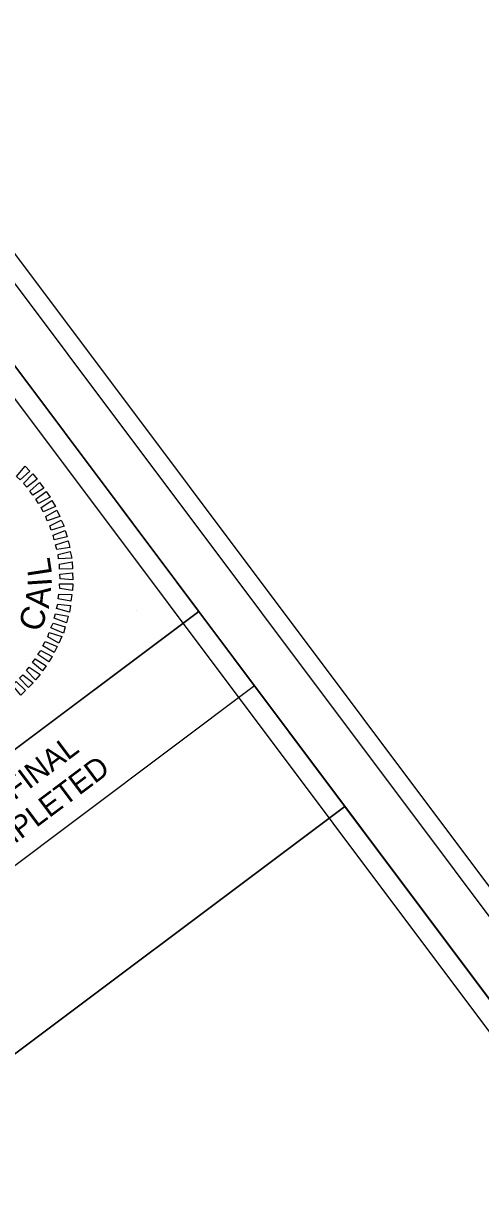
# Model space of a CAD drawing. Extents: x 2186558 to 2188589, y 629855 to 631741.
# Drawn here: x 2187977.7 to 2188093, y 631449 to 631741 of the extents above; entities that cross this region are included whole.
import ezdxf

# ---------------------------------------------------------------- set-up
doc = ezdxf.new("R2010")
doc.units = 0
for name, color, linetype in [('Default', 7, 'Continuous'), ('Scratch_Level_8', 7, 'Continuous'), ('Sheet Plan CELL', 7, 'Continuous'), ('Sheet Plan Layout CELL', 7, 'Continuous'), ('Sheet Plot Border Inside CELL', 7, 'Continuous'), ('Sheet Plot Border Outside CELL', 7, 'Continuous'), ('Sheet Sticker Exception Certification CELL', 7, 'Continuous')]:
    doc.layers.add(name, color=color, linetype=linetype)

msp = doc.modelspace()

# ---------------------------------------------------------------- linework, layer by layer
at = {"layer": 'Default'}
msp.add_line((2188006.11, 631592.93), (2188006.11, 631592.93), dxfattribs=at)
for points in [[(2187976, 631626.73), (2187978.18, 631629.31), (2187979.37, 631628.05), (2187976.93, 631625.91)], [(2187977.74, 631625), (2187980.07, 631627.38), (2187981.19, 631626.06), (2187978.55, 631624.09)], [(2187979.34, 631623.03), (2187981.82, 631625.21), (2187982.86, 631623.83), (2187980.07, 631622.06)], [(2187980.86, 631621.01), (2187983.5, 631622.98), (2187984.45, 631621.55), (2187981.51, 631619.98)], [(2187982.16, 631618.94), (2187984.9, 631620.68), (2187985.77, 631619.19), (2187982.69, 631617.82)], [(2187983.39, 631616.63), (2187986.15, 631618.27), (2187986.9, 631616.68), (2187983.74, 631615.57)], [(2187984.36, 631614.33), (2187987.27, 631615.75), (2187987.99, 631614.21), (2187984.71, 631613.26)], [(2187985.25, 631611.96), (2187988.28, 631613.15), (2187988.73, 631611.53), (2187985.48, 631610.8)], [(2187985.85, 631609.56), (2187989.03, 631610.55), (2187989.4, 631608.87), (2187986.11, 631608.36)], [(2187986.48, 631607.12), (2187989.51, 631607.88), (2187989.89, 631606.2), (2187986.57, 631605.98)], [(2187986.81, 631604.65), (2187990, 631605.2), (2187990.11, 631603.45), (2187986.78, 631603.42)], [(2187986.88, 631602.11), (2187990.11, 631602.44), (2187990.22, 631600.69), (2187986.97, 631600.97)], [(2187986.86, 631599.69), (2187990.19, 631599.72), (2187990.09, 631598), (2187986.87, 631598.49)], [(2187986.67, 631597.07), (2187989.95, 631597), (2187989.71, 631595.3), (2187986.51, 631595.94)], [(2187986.43, 631594.61), (2187989.56, 631594.24), (2187989.31, 631592.54), (2187986.08, 631593.47)], [(2187985.19, 631589.76), (2187988.25, 631588.89), (2187987.81, 631587.29), (2187984.67, 631588.61)], [(2187985.79, 631592.17), (2187989.03, 631591.57), (2187988.58, 631589.9), (2187985.45, 631591.03)], [(2187984.24, 631587.4), (2187987.39, 631586.41), (2187986.65, 631584.78), (2187983.84, 631586.34)], [(2187983.23, 631585.13), (2187986.27, 631583.86), (2187985.44, 631582.35), (2187982.64, 631584.05)], [(2187980.69, 631580.75), (2187983.49, 631579.05), (2187982.5, 631577.74), (2187980.05, 631579.83)], [(2187982.12, 631582.9), (2187984.97, 631581.37), (2187984.16, 631580), (2187981.36, 631581.88)], [(2187979.17, 631578.73), (2187981.98, 631576.84), (2187980.81, 631575.53), (2187978.47, 631577.88)], [(2187975.86, 631575.04), (2187978.26, 631572.85), (2187977.08, 631571.65), (2187974.98, 631574.19)], [(2187977.59, 631576.78), (2187980.2, 631574.75), (2187978.98, 631573.58), (2187976.71, 631575.93)]]:
    msp.add_lwpolyline(points, close=True, dxfattribs=at)
at = {"layer": 'Scratch_Level_8'}
msp.add_lwpolyline([(2186738.7, 630811.99), (2187930.9, 631705.79), (2188554.73, 630873.69), (2187362.53, 629979.89)], close=True, dxfattribs=at)
at = {"layer": 'Sheet Plan CELL'}
for points in [[(2187931.9, 631712.82), (2186731.71, 630813.02), (2187361.55, 629972.91), (2188561.73, 630872.69)], [(2187874.4, 631622.77), (2187954.4, 631682.76), (2188021.9, 631592.74), (2187941.9, 631532.75)], [(2187361.55, 629972.91), (2186731.7, 630812.99), (2187771.81, 631592.82), (2187861.84, 631472.76), (2188021.9, 631592.74), (2188561.73, 630872.69)]]:
    msp.add_lwpolyline(points, close=True, dxfattribs=at)
at = {"layer": 'Sheet Plan Layout CELL'}
for points in [[(2187867.31, 631400.07), (2188058.75, 631543.6), (2187931.91, 631712.83), (2187740.45, 631569.29)], [(2186731.7, 630812.99), (2187361.55, 629972.91), (2188561.72, 630872.68), (2188058.73, 631543.59), (2187867.31, 631400.07), (2187740.45, 631569.29)]]:
    msp.add_lwpolyline(points, close=True, dxfattribs=at)
at = {"layer": 'Sheet Plot Border Inside CELL'}
msp.add_lwpolyline([(2187240.25, 629878.83), (2188573.22, 630878.18), (2187940.39, 631722.3), (2186607.41, 630722.95)], close=True, dxfattribs=at)
at = {"layer": 'Sheet Plot Border Outside CELL'}
msp.add_lwpolyline([(2187241.85, 629855.03), (2188588.83, 630864.88), (2187932, 631741), (2186585.01, 630731.15)], close=True, dxfattribs=at)
at = {"layer": 'Sheet Sticker Exception Certification CELL'}
for p, q in [((2187861.84, 631472.76), (2188021.89, 631592.75)), ((2187861.84, 631472.76), (2188021.89, 631592.75)), ((2188021.9, 631592.74), (2188036, 631573.94)), ((2188021.9, 631592.74), (2188036, 631573.94)), ((2188035.99, 631573.95), (2187875.94, 631453.96)), ((2188035.99, 631573.95), (2187875.94, 631453.96))]:
    msp.add_line(p, q, dxfattribs=at)

# ---------------------------------------------------------------- texts
at = {"layer": 'Default'}
for s, rotation, p in [('L', 98.6701, (2187984.98, 631602.08)), ('A', 83.8455, (2187984.13, 631593.34)), ('I', 93.8014, (2187984.95, 631599.19)), ('C', 73.1407, (2187982.13, 631587.31))]:
    msp.add_text(s, height=6.07, rotation=rotation, dxfattribs=at).set_placement(p)
at = {"layer": 'Sheet Sticker Exception Certification CELL'}
for s, p in [('DOCUMENT NOT CONSIDERED FINAL', (2187884.9, 631477.12)), ('DOCUMENT NOT CONSIDERED FINAL', (2187884.9, 631477.12)), ('UNLESS ALL SIGNATURES COMPLETED', (2187886.12, 631467.04)), ('UNLESS ALL SIGNATURES COMPLETED', (2187886.12, 631467.04))]:
    msp.add_text(s, height=5.5, rotation=36.8593, dxfattribs=at).set_placement(p)

doc.saveas('drawing.dxf')
